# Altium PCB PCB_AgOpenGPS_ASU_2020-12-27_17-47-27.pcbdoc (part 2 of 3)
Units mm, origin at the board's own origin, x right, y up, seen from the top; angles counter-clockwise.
Board outline 200.19 x 135.91 mm, 2 copper layers (Top Layer, Bottom Layer); 260 components, 183 nets, 970 pads, 382 vias.
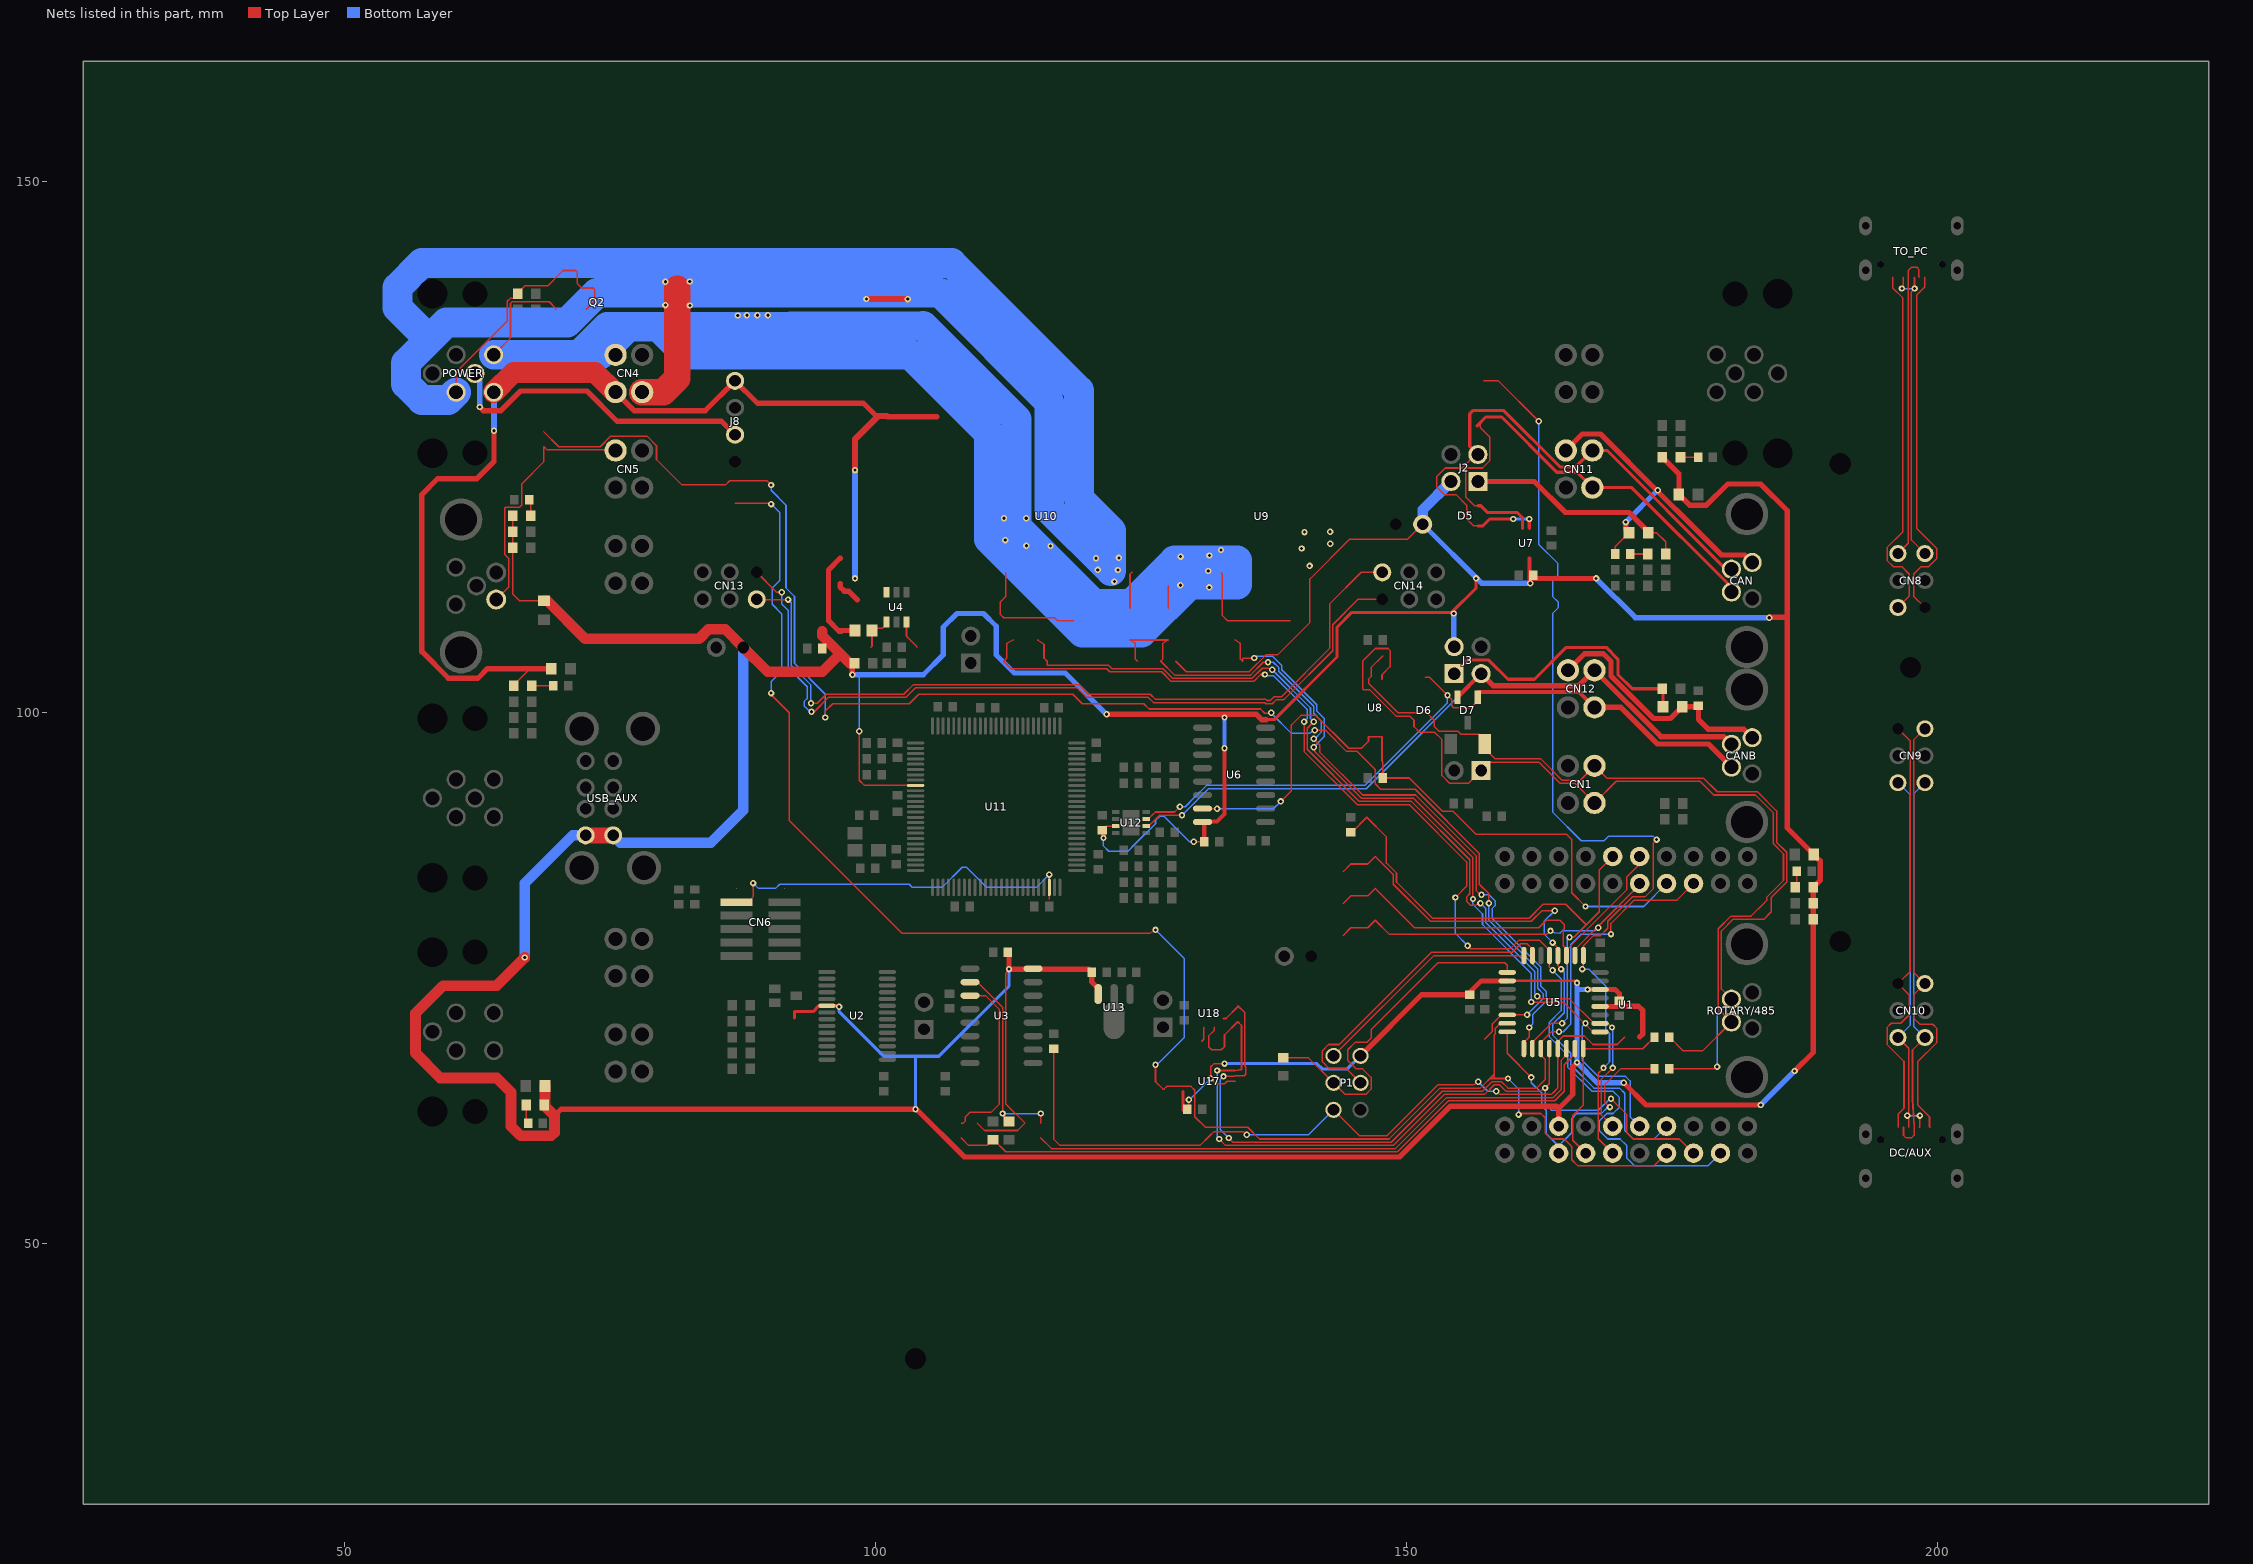
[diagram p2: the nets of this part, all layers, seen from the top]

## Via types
v1: diameter 0.6, hole 0.3, Top Layer to Bottom Layer, 381 vias
v2: diameter 0.61, hole 0.305, Top Layer to Bottom Layer, 1 vias

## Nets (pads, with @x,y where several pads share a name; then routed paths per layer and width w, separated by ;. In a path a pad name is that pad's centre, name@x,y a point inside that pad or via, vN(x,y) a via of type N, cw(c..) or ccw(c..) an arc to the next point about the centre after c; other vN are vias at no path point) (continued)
+5V: 5V.2 C2.1 C4.1 C11.1 C14.1 C22.1 C26.1 C34.1 C35.1 C40.1 C53.1 CHA.2 CHB.2 CN7.1 F1.2 F5.1 F6.1 F7.1 FGNSS.1 FROT.1 FSER.1 FWAS.1 J1.2 J2.2 J3.2 L8.2 P1.2 R6.2 R22.2 R23.2 R48.1 U1.31 U2.20 U3.16 U5.4 U5.6 U5.18 U6.16 U7.3 U11.9 U12.3 U13.3 U17.5 U17.8 USB_AUX.1 USB_AUX.5 WAS1.2 WAS2.2 | length 680.2
  Top Layer w0.145: FWAS.1@65.837,118.5 65.837,111.15 66.488,110.499 F5.1@68.786,110.499 ; FGNSS.1@68.837,63 68.887,63.05 F1.2@68.887,64.8 ; v1(98.486,98.2) 98.486,93.601 98.987,93.1 U11.9@103.787,93.1 ; R22.2@109.587,61.3 110.287,60.6 110.487,60.6 ; C40.1@121.387,88.9 121.757,89.27 U12.3@122.655,89.27 ; R48.1@128.287,104.8 129.286,103.799 135.187,103.799 136.787,105.399 137.887,105.399 140.937,108.45 140.937,112.552 144.687,116.301 150.158,116.301 J1.2@151.557,117.7 ; C14.1@129.387,62.6 129.537,62.75 v1(129.537,63.5) ; v1(129.987,87.8) C4.1@130.987,87.8 ; v1(132.887,66.9) 131.887,66.9 131.588,66.601 131.588,65.501 132.087,65 132.887,65 133.138,65.251 U17.8@133.89,65.251 ; CHB.2@188.337,80.5 188.337,83.5 188.887,84.05 188.887,86.1 F6.1@188.387,86.6
  Top Layer w0.15: 110.487,60.6 113.388,60.6 R23.2@114.087,61.3 112.286,63.1 112.287,75.4 v1(112.587,75.8) 112.632,75.845 U3.16@114.859,75.845
  Top Layer w0.25: U5.18@159.518,74.69 166.089,74.69 v1(166.087,74.5)
  Top Layer w0.3: C26.1@92.387,71.2 92.388,71.8 94.138,71.8 94.689,72.354 95.444,72.354 96.541,72.353 96.587,72.306 v1(96.587,72.25) ; U17.5@128.988,64.251 128.987,62.5 C14.1@129.387,62.6 ; 136.924,99.301 137.587,99.301 143.488,105.201 143.488,108 144.887,109.4 148.588,109.4 154.288,109.4 156.586,111.701 v1(156.587,112.6)
  Top Layer w0.35: U7.3@161.617,114.468 161.617,112.22 v1(161.687,112.15)
  Top Layer w0.4: U6.16@130.815,89.655 U6.16@130.987,89.483 ; C4.1@130.987,87.8 U6.16@130.987,89.483 ; v1@132.888,96.6 132.888,90.4 132.187,89.699 130.988,89.699 U6.16@130.988,89.483
  Top Layer w0.45: C22.1@155.987,73.4 155.987,73.601 157.077,74.69 U5.18@159.518,74.69 ; U5.4@168.255,72.283 170.087,72.283 170.087,73.5 169.688,73.88 ; U5.6@168.255,73.88 169.667,73.88
  Top Layer w0.5: 69.787,62.001 70.386,62.6 103.886,62.6 108.387,58.099 149.386,58.099 154.186,62.9 164.148,62.9 164.366,62.681 ; v1(97.837,103.526) 5V.2@97.837,104.6 ; C35.1@112.487,77.4 112.587,77.3 v1(112.587,75.8) 120.087,75.8 C53.1@120.387,75.5 ; C53.1@120.386,75.501 120.386,74.599 120.988,74 U13.3@120.987,73.45 ; C40.1@121.387,88.9 121.487,88.8 v1(121.487,88.15) ; v1(121.787,99.8) 135.887,99.8 136.387,99.3 136.837,99.3 ; P1.2@145.699,67.632 151.467,73.4 C22.1@155.987,73.4 ; C2.1@161.987,112.9 161.986,112.6 v1(167.887,112.6) ; U1.31@164.367,61 164.367,62.68 165.687,64 165.687,66.6 v1(166.087,67) ; v1(167.087,73.881) U5.6@168.256,73.881 ; C34.1@170.087,72.801 170.087,72.3 171.885,72.3 172.286,71.899 172.286,69.699 171.986,69.4 ; v1(170.487,65.1) 172.587,63 v1(183.387,63) ; FSER.1@174.137,124 175.687,122.45 F7.1@175.687,120.5 176.688,119.501 178.288,119.501 180.287,121.5 183.388,121.5 185.888,119.001 185.888,89.1 F6.1@188.387,86.6 188.987,86 188.987,84.15 188.337,83.5 188.337,67.95 ; v1(184.187,108.9) 184.23,108.943 185.888,108.943 ; v1(186.587,66.2) 188.337,67.95 ; 188.337,68.815 188.337,67.95
  Top Layer w1: v1(66.987,76.9) 64.339,74.251 59.287,74.251 56.688,71.65 56.688,67.898 59.038,65.549 64.339,65.549 65.687,64.2 65.687,61 66.587,60.101 69.487,60.101 69.787,60.4 69.787,62.001 68.888,62.9 F1.2@68.887,64.8 ; F5.1@68.786,110.499 69.086,110.499 72.688,106.9 83.386,106.9 84.288,107.799 85.858,107.799 CN7.1@87.557,106.1 89.858,103.799 94.986,103.799 96.688,105.501 ; 94.987,107.6 94.987,107.2 96.687,105.5 ; 5V.2@97.837,104.6 97.587,104.6 96.687,105.5
  Top Layer w1.5: USB_AUX.1@72.712,88.4 USB_AUX.5@75.313,88.4
  Bottom Layer w0.145: v1(98.486,98.2) 98.486,103.526 ; v1(121.487,88.15) 121.487,87.4 121.987,86.9 123.787,86.9 124.487,87.6 126.387,89.5 126.387,89.8 126.787,90.2 127.187,90.2 127.587,89.8 129.587,87.8 v1(129.987,87.8) ; v1(129.537,63.5) 129.587,63.5 v1(131.587,65.5)
  Bottom Layer w0.3: v1(96.587,72.25) 96.587,71.8 100.787,67.6 105.987,67.6 112.587,74.2 v1(112.587,75.8) ; v1(103.787,62.6) 103.787,67.6 ; v1(132.887,66.9) 141.587,66.9 142.087,66.4 144.467,66.4 P1.2@145.699,67.632
  Bottom Layer w0.4: v1@132.887,96.6 v1(132.887,99.5)
  Bottom Layer w0.5: v1@97.836,103.525 104.514,103.525 106.388,105.399 106.388,108 107.686,109.3 110.188,109.3 111.387,108.099 111.387,105.399 113.086,103.7 117.887,103.7 v1@121.788,99.801 ; J1.2@151.557,117.7 157.107,112.15 v1(161.687,112.15) ; v1@154.487,109.3 154.487,106.2 J3.2@154.517,106.17 ; v1@166.086,66.999 166.086,74 166.205,73.88 v1(167.087,73.881) ; v1(166.087,67) 167.987,65.1 v1(170.487,65.1) ; 166.087,73.9 v1(166.087,74.5) ; v1(167.887,112.6) 171.587,108.9 v1(184.187,108.9) ; v1(183.387,63) v1@186.587,66.2
  Bottom Layer w1: v1(66.987,76.9) 66.988,83.9 71.486,88.399 USB_AUX.1@72.712,88.4 ; USB_AUX.5@75.311,88.399 75.987,87.7 84.486,87.7 87.557,90.771 CN7.1@87.557,106.1 ; J1.2@151.557,117.7 151.557,119.07 J2.2@154.217,121.73
  other v1: 132.887,96.6 154.487,109.3
+BATT: C17.2 C18.2 C19.2 C32.1 CN4.2 D2.1 F4.1 FINP.1 J8.4 POWER.1 U4.3 | length 113.2
  Top Layer w0.145: FINP.1@65.937,102.5 65.937,102.55 67.487,104.1 F4.1@69.487,104.1
  Top Layer w0.5: v1@64.087,126.501 64.087,123.601 62.487,122 58.786,122 57.288,120.499 57.288,105.701 59.787,103.199 62.586,103.199 63.488,104.101 F4.1@69.487,104.101 ; CN4.2@75.537,130.15 77.287,128.4 83.977,128.4 J8.4@86.787,131.21 88.897,129.1 98.887,129.1 100.087,127.9 C32.1@101.087,127.9 101.152,127.835 D2.1@105.787,127.835 ; C17.2@96.687,112.1 96.688,111.8 97.087,111.401 97.488,111.401 98.288,110.601
  Top Layer w0.6: v1@98.088,122.801 98.088,125.701 100.287,127.901 101.087,127.901
  Top Layer w2: POWER.1@64.054,130.131 65.924,132 73.588,131.994 CN4.2@75.487,130.151
  Bottom Layer w0.6: POWER.1@64.055,130.132 64.087,130.1 v1(64.087,126.5) ; v1(98.087,112.6) v1(98.087,122.8)
+MOTOR: C30.2 C31.1 CN4.1 D1.1 MOT.2 POWER.4 Q2.2 R51.2 R53.2 U9.7 U10.7 | length 231.6
  Top Layer w0.145: POWER.4@60.519,130.132 60.519,132.031 65.337,136.849 65.337,138.701 65.639,139.001 66.338,139.001 MOT.2@66.337,139.4 ; MOT.2@66.338,139.407 66.338,139.501 66.988,140.149 69.137,140.149 70.437,141.449 70.587,141.6 ; 123.988,109.801 123.988,113.001 C30.2@124.187,113.2
  Top Layer w0.15: 70.587,141.599 71.789,141.599 71.938,141.449 71.938,140.349 72.337,139.951 73.437,139.951 73.587,139.801 73.587,138.757 Q2.2@72.771,137.94
  Top Layer w0.6: v1(99.155,138.912) v1(103.053,138.907)
  Top Layer w2.5: CN4.1@78.037,130.151 80.038,130.151 81.352,131.465 D1.1@81.352,139.9
  Bottom Layer w2.8: 57.986,135.089 54.986,138.089 54.986,140.001 57.285,142.3 107.186,142.3 119.187,130.299 119.187,120.101 122.187,117.101 122.187,113.301 116.388,119.1 116.388,129.239 106.124,139.501 ; POWER.4@60.519,130.132 59.787,129.4 57.288,129.4 55.787,130.901 55.787,132.9 59.586,136.699 70.986,136.699 73.787,139.501 106.086,139.501
  other v1: 122.517,112.301 122.842,113.396 120.947,113.406 140.904,113.779 120.779,114.495 122.939,114.532 140.152,115.416 142.842,115.858 140.425,116.958 142.833,116.996 82.535,138.3 80.224,138.338 80.224,140.548 82.522,140.561
+SMPS: C20.2 C21.2 L7.2 L8.1 R17.2 | length 9.5
  Top Layer w0.5: C21.2@96.687,114.5 95.588,113.4 95.588,108.617 96.604,107.601 ; 96.787,107.601 96.604,107.601 ; R17.2@98.087,107.7 96.703,107.7 96.604,107.601
-MOTOR: C30.1 C31.2 CN4.4 D1.2 POWER.2 R11.1 R12.1 R20.2 R21.2 R49.1 R54.2 U9.1 U10.1 | length 206.3
  Top Layer w0.145: POWER.2@64.054,133.669 65.639,135.252 65.639,138.498 65.792,138.65 ; U10.1@112.277,113.116 112.277,110.89 111.787,110.4 111.787,109.2 112.087,108.9 116.888,108.9 R21.2@117.187,108.6 R20.2@118.687,108.6 ; R54.2@127.587,109.8 127.587,111.9 ; U9.1@132.577,113.116 132.687,113.006 132.687,109.1 133.187,108.6 R11.1@137.587,108.6 R12.1@139.087,108.6
  Top Layer w0.15: 65.787,138.65 69.287,138.65 69.887,138.05 R49.1@69.887,137.9
  Bottom Layer w2.8: POWER.2@64.054,133.669 74.067,133.669 76.698,136.301 ; 72.162,133.682 74.793,136.313 ; 74.76,136.301 76.698,136.301 ; 79.185,136.301 104.487,136.4 113.287,127.601 113.287,117.5 120.587,110.2 124.087,110.2 128.187,114.299 134.087,114.299 134.087,112.001 129.586,112.001 125.085,107.5 119.487,107.5 110.686,116.301 110.686,126.301 103.287,133.7 82.187,133.7 79.586,136.301 76.698,136.301
  other v1: 131.452,111.759 128.734,111.953 131.349,113.294 128.756,114.65 131.461,114.752 132.555,115.282 116.504,115.651 114.229,115.668 112.229,116.206 112.115,118.266 114.215,118.263 87.04,137.366 87.904,137.379 88.894,137.379 89.885,137.379
.8V: R17.1 R18.2 U4.4 | length 3.5
  Top Layer w0.145: R18.2@99.587,106.1 99.687,106.2 R17.1@99.687,107.7 99.887,107.9 100.687,107.9 101.037,108.25 U4.4@101.037,108.5
_RESET: C7.1 P1.5 R6.1 U5.29 | length 73.3
  Top Layer w0.145: C7.1@116.787,68.3 116.787,59.8 117.387,59.2 130.587,59.2 131.487,60.1 131.887,60.5 133.287,60.5 134.687,60.5 v1(134.987,60.2) ; P1.5@143.159,62.552 145.611,60.101 148.187,60.101 152.987,64.901 156.387,64.9 v1@156.787,65.201 ; v1(158.487,64.3) 158.787,64 160.387,64 163.687,64 163.887,64.2 164.281,64.594 U5.29@164.281,68.319 164.281,68.994 164.787,69.5 166.787,69.5 167.587,68.7 169.887,68.7 R6.1@170.587,69.4
  Bottom Layer w0.145: v1(134.987,60.2) 140.807,60.2 P1.5@143.159,62.552 ; v1(156.787,65.2) 157.687,64.3 v1(158.487,64.3)
_RESETNXP: CN6.10 U11.48 | length 35.8
  Top Layer w0.145: CN6.10@86.937,82.105 87.992,82.105 88.487,82.6 v1@88.487,83.9 ; 116.387,82.4 U11.48@116.387,83.5 v1(116.387,84.7)
  Bottom Layer w0.145: v1@88.486,83.9 88.987,83.4 90.587,83.4 90.988,83.799 103.188,83.799 103.488,83.499 106.287,83.499 108.187,85.399 108.588,85.399 110.488,83.499 115.187,83.499 v1@116.388,84.701
  other v1: 88.487,83.9
_RXD: R9.2 RXD.1 U3.2 | length 19.6
  Top Layer w0.145: U3.2@108.915,74.575 109.613,74.575 111.987,72.201 111.987,62.049 RXD.1@112.586,61.449 ; R9.2@115.587,61.3 v1(115.587,62.2)
  Bottom Layer w0.145: v1(111.987,62.2) v1(115.587,62.2)
_TXD: R7.1 U3.3 | length 16.8
  Top Layer w0.145: R7.1@108.087,61.3 108.288,61.3 108.486,61.5 108.486,61.899 108.888,62.3 110.887,62.3 111.687,63.101 111.687,72 110.382,73.305 U3.3@108.915,73.305
A: CN1.4 D6.1 J4.1 R32.1 R37.1 R90.1 ROTARY/485.4 U8.6 | length 90
  Top Layer w0.145: R37.1@146.387,105.3 147.087,106 148.287,106 148.487,105.8 148.487,104.3 147.722,103.535 U8.6@147.722,103.12 ; R37.1@146.387,105.3 145.888,104.8 145.888,102.201 145.987,102.1 146.586,102.1 149.088,99.6 150.386,99.6 150.737,99.25 150.737,99.001 150.737,98.65 151.288,98.099 152.688,98.099 153.363,97.423 153.363,94.025 154.087,93.301 155.857,93.301 157.056,94.5 157.056,95.3 162.487,95.3 164.488,93.301 165.888,93.301 CN1.4@167.737,91.45 169.787,93.499 177.663,93.499 178.961,92.201 182.888,92.201 184.587,90.499 184.587,87.599 185.537,86.651 185.537,84.15 183.945,82.557 183.945,82.258 R32.1@183.687,82 182.487,80.799 180.587,80.799 179.388,79.6 179.388,72.074 ROTARY/485.4@180.637,70.825 ; R90.1@174.787,69.4 176.089,68.099 177.915,68.099 ROTARY/485.4@180.427,70.614
A0/WAS: C9.2 R28.2 U1.16 U5.23 U17.4 | length 159.5
  Top Layer w0.145: R28.2@86.787,119.7 90.087,119.7 v1(90.187,119.6) ; v1(90.187,101.8) 90.188,101.65 91.888,99.951 91.888,89.798 102.487,79.199 125.888,79.199 v1@126.388,79.501 ; v1(126.387,66.8) 126.387,65.2 127.087,64.5 C9.2@127.187,64.5 127.438,64.751 U17.4@128.988,64.751 ; U17.4@128.988,64.751 129.736,64.749 130.087,64.398 130.087,61.899 131.087,60.898 135.088,60.898 136.188,59.801 137.287,59.801 148.387,59.801 153.188,64.599 156.988,64.599 158.288,65.902 158.288,69.6 158.387,69.699 158.387,70.2 158.88,70.692 U5.23@159.518,70.692 ; 157.821,65.433 157.888,65.501 158.288,65.501 ; 158.288,66.339 158.288,65.501 ; v1@159.586,65.501 158.288,65.501 ; v1(160.587,62.1) 160.686,62.201 162.687,62.201 163.086,61.8 163.086,60.4 163.688,59.801 164.887,59.801 165.588,59.1 165.588,57.853 166.139,57.299 173.368,57.299 U1.16@174.526,58.46
  Bottom Layer w0.145: v1(90.187,101.8) 90.188,102.9 91.186,103.9 91.186,109.257 90.287,110.156 90.287,111.701 90.988,112.402 90.988,118.8 v1(90.187,119.6) ; v1@126.388,66.801 126.538,66.801 129.088,69.349 129.088,76.801 v1@126.388,79.501 ; v1(159.587,65.5) 160.587,64.5 v1(160.587,62.1)
  other v1: 126.387,79.5
A1/CH_B: R91.2 U1.32 U5.24 | length 28.9
  Top Layer w0.145: U5.24@159.518,69.893 159.518,67.869 v1(161.787,65.6) ; v1@169.187,62.801 168.687,63.301 168.687,64.899 170.188,66.4 R91.2@173.386,66.4
  Bottom Layer w0.145: v1(161.787,65.6) 161.787,65.1 162.787,64.1 162.787,62.936 163.187,62.5 163.187,60.3 164.366,59.121 164.366,58.46 164.366,59.179 165.588,60.4 165.588,61.701 166.089,62.201 168.387,62.201 168.987,62.801 v1@169.187,62.801
  other v1: 169.187,62.8
A2/SAFESENSE: R25.1 R48.2 R53.1 R54.1 U5.25 | length 72.2
  Top Layer w0.145: R25.1@124.687,104.8 124.486,105 124.486,106.499 R53.1@123.987,106.8 R54.1@127.587,106.8 127.087,106.499 127.087,105 126.886,104.8 128.187,103.499 135.337,103.499 136.538,104.701 v1@136.988,104.701 ; v1(141.287,97.5) 141.847,96.941 141.847,96.263 145.911,92.201 150.887,92.201 156.586,86.499 156.586,83.199 156.986,82.8 v1(157.087,82.8) ; U5.25@161.082,68.318 161.082,68.897 161.588,69.4 v1@161.588,70.301
  Bottom Layer w0.145: v1@136.988,104.701 137.488,104.701 137.986,104.2 137.986,103.85 141.288,100.55 141.288,99.9 141.986,99.199 141.986,98.099 141.387,97.5 v1(141.287,97.5) ; v1@157.087,82.801 157.808,82.801 158.387,82.222 158.387,81.8 158.088,81.5 158.088,80.601 162.682,76.006 162.682,74.205 163.188,73.699 163.188,72.801 161.937,71.55 161.937,70.65 v1(161.587,70.3)
  other v1: 136.987,104.7
A3/OUT: R33.2 R77.1 U1.21 U5.26 | length 52.1
  Top Layer w0.145: R77.1@144.787,88.7 144.887,88.7 R33.2@146.287,90.1 148.137,88.25 148.137,85.796 149.088,84.845 149.087,84 152.487,80.6 161.587,80.6 162.887,81.9 165.036,81.9 166.961,79.974 ; U5.26@161.883,68.319 161.883,68.896 163.687,70.7 v1(164.687,70.7) ; v1(165.387,78.8) 165.787,78.8 167.287,80.3 168.187,81.2 168.187,83 168.187,85.14 U1.21@169.447,86.4
  Bottom Layer w0.145: v1(164.687,70.7) 165.187,71.2 165.187,78.8 v1(165.387,78.8)
A4/SDA: R30.1 U1.10 U5.27 U17.9 U18.6 | length 79.2
  Top Layer w0.145: v1(132.787,65.7) 133.84,65.7 U17.9@133.89,65.751 134.738,65.751 134.887,65.9 134.887,66.6 134.787,66.7 134.787,71.703 134.139,72.351 134.139,72.252 133.038,71.151 U18.6@132.789,71.151 ; v1(133.287,59.9) 133.688,59.501 148.588,59.501 153.386,64.299 157.188,64.299 158.09,65.201 158.987,65.201 159.589,64.599 162.286,64.599 163.086,65.399 163.086,67.299 162.682,67.703 U5.27@162.682,68.318 ; U5.27@162.683,68.319 162.683,68.896 163.687,69.9 v1(164.387,69.9) ; v1(169.287,79.1) 169.287,80.1 171.487,82.3 175.507,82.3 U1.10@177.067,83.86
  Bottom Layer w0.145: v1(132.787,65.7) 132.487,65.399 132.487,60.7 v1(133.287,59.9) ; v1(164.387,69.9) 164.788,69.9 165.487,70.601 165.487,78.099 166.487,79.1 v1(169.287,79.1)
A5/SCL: R29.1 U1.12 U5.28 U17.10 U18.4 | length 77
  Top Layer w0.145: U18.4@131.939,70.301 131.939,70.052 131.387,69.5 131.387,68.5 131.687,68.2 132.587,68.2 132.887,68.5 132.887,69.599 R29.1@134.139,70.851 134.488,70.503 134.488,66.348 U17.10@133.89,66.251 v1(132.187,66.25) ; v1@132.388,59.801 132.987,59.199 148.786,59.199 153.587,64 157.387,64 158.288,64.901 158.786,64.901 159.388,64.299 162.587,64.3 v1@163.086,64.599 ; v1(163.087,64.6) 163.483,64.996 U5.28@163.483,68.319 ; v1@169.286,63.601 170.788,62.1 170.788,60.4 171.387,59.801 175.728,59.801 U1.12@177.066,58.46
  Bottom Layer w0.145: v1(132.187,66.25) 132.187,60 v1(132.387,59.8) ; v1@163.086,64.599 163.086,63.1 163.688,62.501 168.088,62.501 169.187,63.601 v1@169.286,63.601
  other v1: 169.287,63.6
A7: C33.2 R5.2 R56.2 U5.22 | length 143.1
  Top Layer w0.145: 68.786,126.4 70.186,125 74.087,125 75.088,126.001 78.486,126.001 79.388,125.099 79.388,123.801 81.794,121.401 85.888,121.401 86.287,121.8 87.288,121.8 89.787,121.8 v1(90.187,121.4) ; v1@95.286,99.501 95.286,100.101 95.987,100.799 103.185,100.799 104.087,101.701 118.588,101.701 119.487,100.799 125.286,100.799 125.786,100.301 136.287,100.301 136.688,99.9 v1@137.287,99.9 ; v1(141.387,98.3) 142.388,98.3 144.387,96.301 145.388,96.301 R5.2@146.387,95.3 147.087,94.599 147.087,93.25 147.587,92.75 150.846,92.75 156.886,86.7 156.886,83.799 157.788,82.9 v1@157.788,82.001 ; C33.2@157.387,69.2 158.088,69.9 158.088,70.601 158.982,71.493 U5.22@159.518,71.493 ; U5.22@159.518,71.494 161.381,71.493 v1(161.387,71.5)
  Bottom Layer w0.145: v1@90.188,121.401 90.188,120.901 91.588,119.501 91.588,111.701 92.388,110.901 92.388,104.599 95.286,101.701 v1@95.286,99.501 ; v1@137.287,99.9 139.187,98 140.887,98 v1(141.387,98.3) ; v1@157.788,82.001 157.788,80.4 162.385,75.803 162.385,74.002 162.888,73.499 162.888,73.001 v1(161.387,71.5)
  other v1: 157.787,82 95.287,99.5 137.287,99.95
AUX: J8.2 POWER.5 | length 30
  Top Layer w0.5: v1(62.737,128.75) 63.086,128.399 64.737,128.399 66.587,130.25 72.838,130.25 75.687,127.401 85.517,127.401 J8.2@86.787,126.13
  Bottom Layer w0.5: POWER.5@62.287,131.9 62.737,131.45 v1(62.737,128.75)
B: CN1.2 D6.2 R31.1 R38.1 R91.1 R92.2 ROTARY/485.2 U8.7 | length 82.9
  Top Layer w0.145: 146.452,103.121 146.688,103.354 146.688,104.2 R38.1@147.787,105.3 ; U8.7@146.452,103.12 146.452,102.735 149.259,99.929 151.958,99.929 152.637,99.25 D6.2@152.637,99 ; 152.637,99.001 152.637,98.65 153.086,98.201 154.887,98.201 155.187,97.901 156.886,97.901 157.387,97.401 R92.2@157.387,97 ; R92.2@157.087,96.199 157.785,96.199 158.387,95.6 162.687,95.6 164.686,93.601 166.386,93.601 CN1.2@167.737,94.95 ; CN1.2@167.737,94.95 168.888,93.799 173.555,93.799 ; 173.188,93.799 177.988,93.799 179.286,92.501 183.086,92.501 184.887,90.7 184.887,87.751 185.837,86.801 185.837,84 184.387,82.549 184.387,81.2 R31.1@183.687,80.5 ; R91.1@174.787,66.4 179.087,66.4 v1@179.287,66.6 ; ROTARY/485.2@180.637,72.975 179.687,73.925 179.687,79.4 180.787,80.5 R31.1@183.687,80.5
  Bottom Layer w0.145: v1(179.287,66.6) 179.287,71.623 ROTARY/485.2@180.637,72.975
C8_2: C8.2 U18.2 | length 1.4
  Top Layer w0.145: C8.2@130.737,69 130.939,69.202 U18.2@130.939,70.301
C16_1: C16.1 U4.6 | length 2.8
  Top Layer w0.145: U4.6@102.937,108.5 102.937,107.151 103.887,106.2 C16.1@103.887,106.1
CAN+: CAN.1 CN11.1 F2.2 R71.2 | length 31.2
  Top Layer w0.145: R71.2@169.687,114.9 169.687,115.6 F2.2@170.987,116.9
  Top Layer w0.5: CN11.1@165.037,124.65 166.586,126.199 168.288,126.199 170.988,123.499 ; v1(170.687,117.9) 170.687,117.2 F2.2@170.987,116.9 ; CAN.1@182.588,114.101 181.887,114.8 179.683,114.8 171.036,123.446 ; 170.988,123.499 171.036,123.446 ; 170.988,123.499 171.036,123.446
  Bottom Layer w0.5: v1(170.687,117.9) v1(173.687,120.9)
CANB+: CANB.1 CN12.1 F3.2 R72.2 | length 23.7
  Top Layer w0.5: CN12.1@165.237,103.95 166.787,105.5 168.587,105.5 169.287,104.8 169.287,103.4 173.287,99.4 174.887,99.4 F3.2@175.987,100.5 177.533,100.5 177.533,99.304 178.437,98.4 181.788,98.4 CANB.1@182.587,97.6
CANH: CAN.4 CN11.4 D5.2 R60.1 U7.7 | length 47.5
  Top Layer w0.145: D5.2@156.787,119.45 156.437,119.45 155.588,120.301 155.588,122.806 155.784,123.001 157.188,123.001 157.887,123.7 157.887,125.899 156.988,126.801 156.988,127.101
  Top Layer w0.3: 156.698,126.987 157.511,127.799 158.987,127.799 164.186,122.6 166.089,122.6 CN11.4@167.537,121.15 171.237,121.15 180.638,111.749 CAN.4@180.637,111.325 ; D5.2@156.787,119.45 157.036,119.45 157.686,118.8 160.488,118.8 160.958,118.33 U7.7@160.957,117.333
CANH1: CANB.4 CN12.4 D7.1 R65.1 U12.7 | length 68
  Top Layer w0.145: U12.7@125.52,89.93 125.717,89.93 126.187,90.4 126.387,90.6 127.187,90.6 128.187,90.6 v1(128.687,91.1) ; R65.1@151.787,103.3 152.187,103.3 154.287,101.2 154.287,100.6 154.487,100.4 156.087,100.4 156.737,101.05 D7.1@156.737,101.4
  Top Layer w0.4: D7.1@156.737,101.4 156.79,101.899 166.289,101.899 CN12.4@167.737,100.451
  Top Layer w0.5: CN12.4@167.737,100.451 170.236,100.451 173.688,96.999 178.463,96.999 CANB.4@180.637,94.825
  Bottom Layer w0.145: v1(128.687,91.1) 129.187,91.1 130.087,92 131.187,93.1 131.787,93.1 146.087,93.1 153.887,100.9 v1@153.887,101.6
  other v1: 153.887,101.6
CANL: CAN.2 CN11.2 D5.1 J2.3 U7.6 | length 54.2
  Top Layer w0.145: J2.3@156.757,124.271 156.558,124.271 155.288,123.001 153.688,123.001 152.888,122.201 152.888,121.2 153.587,120.499 154.686,120.499 155.687,119.501 155.687,118.201 156.337,117.55 D5.1@156.787,117.55
  Top Layer w0.3: J2.3@156.757,124.27 155.987,125.041 155.987,128.099 156.287,128.401 159.187,128.401 164.488,123.1 165.987,123.1 167.536,124.65 168.936,124.65 180.112,113.476 CAN.2@180.638,113.476 ; D5.1@156.787,117.55 157.237,117.55 157.887,118.201 v1@160.087,118.201 ; v1(161.587,118.2) 161.587,117.363 U7.6@161.617,117.333
  Bottom Layer w0.3: v1(160.087,118.2) v1(161.587,118.2)
CANL1: CANB.2 CN12.2 D7.2 J3.3 U12.6 | length 68.7
  Top Layer w0.145: U12.6@125.52,89.27 125.757,89.27 126.087,89.6 126.787,90.3 v1(128.887,90.3)
  Top Layer w0.4: D7.2@154.836,101.401 J3.3@157.056,103.631 ; D7.2@154.837,101.4 155.241,101.807
  Top Layer w0.5: J3.3@157.057,103.63 158.187,102.5 166.286,102.5 167.737,103.951 173.988,97.7 179.911,97.7 CANB.2@180.637,96.975
  Bottom Layer w0.145: v1(128.887,90.3) 131.387,92.8 146.227,92.8 J3.3@157.057,103.63
CC11: CN8.1 TO_PC.A5 | length 34
  Top Layer w0.145: TO_PC.A5@198.837,140.985 198.837,140.05 198.087,139.3 198.087,117.3 199.987,115.4 199.987,114.5 199.187,113.7 198.487,113.7 197.787,113 197.787,110.93 CN8.1@198.857,109.86
CC12: CN9.1 CN10.1 DC/AUX.A5 | length 41.2
  Top Layer w0.145: CN10.1@196.317,74.44 197.386,73.37 197.386,71.5 196.586,70.7 195.687,70.7 195.288,70.301 195.288,68.701 196.886,67.101 196.887,62.7 196.337,62.15 DC/AUX.A5@196.337,60.915 ; CN9.1@196.317,98.44 197.487,97.27 197.487,75.61 CN10.1@196.317,74.44
CC21: CN8.2 TO_PC.B5 | length 33.9
  Top Layer w0.145: TO_PC.B5@195.837,140.985 195.837,139.951 196.787,139.001 196.787,116.999 195.288,115.501 195.288,114.299 195.888,113.7 196.688,113.7 197.386,113.001 197.386,110.931 CN8.2@196.317,109.86
CC22: CN9.2 CN10.2 DC/AUX.B5 | length 41.7
  Top Layer w0.145: CN10.2@198.857,74.44 197.788,73.37 197.788,71.2 198.387,70.601 199.586,70.601 199.987,70.2 199.987,68.899 198.187,67.098 198.187,63.001 199.286,61.899 199.286,60.964 199.337,60.916 ; CN9.2@198.857,98.44 197.787,97.37 197.787,75.51 CN10.2@198.857,74.44
CN5_4: CN5.4 OP1.2 R56.1 R57.1 | length 24.2
  Top Layer w0.145: OP1.2@64.288,110.611 65.487,111.81 65.487,114.449 65.088,114.85 65.088,116.28 65.088,116.4 65.088,119.199 65.187,119.3 66.488,119.3 66.687,119.5 66.688,119.651 66.688,121.5 68.786,123.601 ; R57.1@68.787,123.6 R56.1@68.787,125 69.087,124.7 75.487,124.7 CN5.4@75.537,124.65
CN13_1: CN13.1 CN14.1 | length 76.7
  Top Layer w0.145: CN13.1@88.827,113.17 90.697,111.3 v1(91.187,111.3) ; v1(93.987,100.05) 94.237,100.05 95.588,101.401 102.888,101.401 103.787,102.3 118.984,102.3 119.883,101.401 125.687,101.401 126.188,100.901 135.388,100.901 136.668,100.901 136.767,100.799 137.387,100.799 137.747,101.16 138.448,101.16 138.512,101.223 ; 138.486,101.2 143.084,105.798 143.084,108.246 145.469,110.631 147.747,110.631
  Bottom Layer w0.145: v1(91.187,111.3) 91.186,110.2 91.786,109.6 91.786,104.2 93.589,102.397 93.589,101.302 93.287,101 93.287,100.601 93.838,100.05 v1(93.987,100.05)
CN13_2: CN13.2 CN14.2 | length 76.2
  Top Layer w0.145: CN13.2@88.827,110.63 88.857,110.6 v1(91.787,110.6) ; v1(93.937,100.85) 94.537,100.85 95.388,101.701 102.688,101.701 103.587,102.6 119.149,102.6 120.048,101.701 125.888,101.701 126.388,101.2 136.787,101.2 136.886,101.101 137.188,101.101 137.544,101.457 138.245,101.457 142.787,106.001 142.787,110.2 145.758,113.171 CN14.2@147.747,113.171
  Bottom Layer w0.145: v1@91.786,110.601 92.087,110.3 92.087,104.401 93.937,102.551 v1(93.937,100.85)
D0/RX: R9.1 U5.30 | length 55.8
  Top Layer w0.145: R9.1@115.587,59.9 116.587,58.9 148.987,58.9 153.787,63.7 163.844,63.7 164.587,64.443 164.587,67.2 165.081,67.694 U5.30@165.081,68.319
D1/TX: R7.2 TXD.1 U5.31 | length 64.6
  Top Layer w0.145: R7.2@108.087,59.9 108.787,59.2 110.537,59.2 TXD.1@111.087,59.75 111.138,59.75 112.286,58.6 149.187,58.6 153.988,63.4 163.988,63.4 164.887,64.299 164.887,66.801 165.88,67.794 U5.31@165.88,68.318
D2/CH_A: R90.2 U1.28 U5.32 | length 17.9
  Top Layer w0.145: U5.32@166.68,68.3 172.286,68.3 R90.2@173.386,69.4 ; U5.32@166.681,68.319 166.681,62.994 165.687,62 165.687,59.68 U1.28@166.907,58.46
D3/PWM0: R27.1 R55.1 U1.19 U5.1 | length 73.3
  Top Layer w0.145: R55.1@133.887,106.8 134.387,106.499 134.387,105 R27.1@134.587,104.8 134.587,105.099 v1(135.687,105.1) ; v1(141.287,96.7) 141.387,96.7 141.387,96.301 145.786,91.899 150.686,91.899 156.287,86.301 v1(156.287,82.4) ; v1(161.787,72.7) 164.788,72.699 167.605,69.882 U5.1@168.255,69.882
  Bottom Layer w0.145: v1(135.687,105.1) 135.687,105.249 137.437,105.249 138.283,104.403 138.283,104.005 141.585,100.703 141.585,100.103 142.286,99.4 142.286,97.7 v1(141.287,96.7) ; v1(156.287,82.4) 156.287,81.899 157.188,81 157.188,79.999 161.788,75.399 v1(161.787,72.7) ; v1@166.886,70.7 166.586,70.4 166.586,67.2 168.088,65.699 170.663,65.699 171.087,65.275 171.087,61.899 U1.19@171.986,61
  other v1: 166.887,70.7
D4/INH: R42.1 R61.1 U1.23 U5.2 | length 88.9
  Top Layer w0.145: R61.1@115.287,106.8 115.887,106.4 115.887,105.1 R42.1@116.187,104.8 ; R42.1@116.187,104.8 116.188,104.401 121.987,104.401 122.286,104.101 127.087,104.101 127.986,103.199 135.487,103.199 136.437,104.149 136.987,104.15 v1(137.387,104) ; v1(141.287,99.1) 140.683,98.495 140.683,96.504 145.588,91.599 150.488,91.599 155.987,86.1 155.987,82.9 155.687,82.6 155.687,82.201 156.086,81.8 156.487,81.8 v1@156.988,82.001 ; v1(162.337,73.25) 162.588,72.999 165.387,72.999 167.704,70.682 U5.2@168.255,70.682 ; U5.2@168.256,70.683 169.004,70.683 v1(169.387,70.3) ; U1.23@169.446,61 168.387,62.059 168.387,65.44 v1(169.447,66.5)
  Bottom Layer w0.145: v1(137.387,104) 140.988,100.398 140.988,99.397 v1@141.288,99.097 ; v1@156.988,82.001 157.488,81.5 157.488,80.2 162.088,75.597 162.088,73.499 v1(162.337,73.25) ; v1(169.387,70.3) 169.447,70.24 v1@169.447,66.5
  other v1: 156.987,82
D5/SERVO: R59.1 U1.24 U5.9 | length 92.1
  Top Layer w0.145: R59.1@157.287,131.2 158.687,131.2 v1@162.487,127.4 ; v1(166.587,75.8) 166.691,75.904 U5.9@166.691,77.082 ; U5.9@166.691,77.081 166.691,78.005 167.653,78.968 168.303,78.968 168.987,79.651 168.987,80.299 171.288,82.6 172.487,82.6 173.287,83.4 173.287,87.7 v1(173.587,88) ; v1(168.587,66.5) 168.088,66.001 168.088,59.821 U1.24@169.446,58.46
  Bottom Layer w0.145: v1@162.487,127.401 162.487,115.8 164.288,113.999 164.288,112.9 163.787,112.399 163.787,110.901 164.336,110.352 164.336,109.849 163.787,109.3 163.787,90.601 166.487,87.901 168.634,87.901 169.035,88.302 173.284,88.302 v1(173.587,88) ; v1(166.587,75.8) 167.187,75.8 168.787,74.2 168.786,70.119 169.15,69.755 169.15,67.063 v1(168.587,66.5)
  other v1: 162.487,127.4
D6/STSW: C28.2 R43.1 U1.18 U5.10 | length 34.9
  Top Layer w0.145: R43.1@144.087,79 144.787,79.7 146.387,79.7 C28.2@147.087,80.4 ; C28.2@147.087,80.4 148.387,79.1 163.287,79.1 v1(163.587,79.4) ; U5.10@165.89,77.081 165.89,77.655 167.836,79.6 167.988,79.6 v1(168.087,79.7) ; v1(168.087,79.7) 168.037,79.75 168.037,79.801 171.986,83.751 U1.18@171.986,83.86
  Bottom Layer w0.145: v1(163.587,79.4) 163.987,79.209 164.486,79.199 164.687,79.4 167.787,79.4 v1(168.087,79.7)
D7/WKSW: C29.2 R46.1 U1.17 U5.11 | length 38.6
  Top Layer w0.145: 144.087,82 144.787,82.7 146.387,82.7 C29.2@147.087,83.4 ; C29.2@147.087,83.4 150.788,79.699 162.487,79.699 163.188,80.4 164.486,80.4 164.887,79.999 164.887,79.6 164.788,79.501 164.788,77.998 165.09,77.695 U5.11@165.09,77.081 ; U5.11@165.091,77.082 165.091,77.604 170.787,83.3 170.787,84.5 171.987,85.7 U1.17@171.987,86.4
D8/RTSW: C27.2 R39.1 U1.15 U5.12 | length 55.3
  Top Layer w0.145: R39.1@144.087,85 144.787,85.7 146.387,85.7 C27.2@147.087,86.4 ; C27.2@147.087,86.4 148.786,84.701 148.786,83.799 152.286,80.301 161.788,80.301 162.787,81.3 v1(163.987,81.3) ; v1(163.787,78.3) 164.291,77.796 U5.12@164.291,77.082 ; U5.12@164.29,77.081 164.29,76.097 v1(164.587,75.8)
  Bottom Layer w0.145: v1(163.787,78.3) 162.987,79.1 162.987,80.299 v1(163.987,81.3) ; v1(164.587,75.8) 164.887,75.5 164.887,71.701 163.787,70.601 163.787,69.603 165.504,67.886 165.504,66.783 167.689,64.599 170.089,64.599 170.587,64.101 170.587,60.601 171.387,59.801 173.328,59.801 U1.15@174.526,61
D9/PWM1: R26.1 R62.2 U1.8 U5.13 | length 111.6
  Top Layer w0.145: R62.2@112.987,106.8 112.388,106.499 112.388,105.099 R26.1@112.087,104.8 112.787,104.101 121.788,104.101 122.088,103.799 126.968,103.799 127.867,102.9 135.637,102.9 136.287,103.55 v1(136.687,103.55) ; v1@140.386,99.1 140.386,96.301 145.388,91.3 150.287,91.3 155.687,85.899 155.687,83.6 v1(154.637,82.55) ; v1(155.787,78) 156.089,77.698 159.787,77.7 160.587,78.5 162.588,78.5 163.493,77.584 U5.13@163.493,77.081 ; U5.13@163.494,77.082 163.494,75.994 v1(163.787,75.7)
  Bottom Layer w0.145: v1@136.787,103.4 136.687,103.5 v1(136.687,103.55) 136.688,103.451 137.488,103.451 140.686,100.25 140.686,99.4 v1@140.46,99.174 ; v1(154.637,82.55) 154.637,79.15 v1(155.787,78) ; v1(163.787,75.7) 164.587,74.899 164.587,71.899 163.488,70.799 163.488,69.415 165.202,67.7 165.202,66.585 167.488,64.299 169.487,64.299 170.087,63.7 170.087,62.801 169.487,62.201 168.888,62.201 168.187,61.5 168.187,60.601 168.987,59.801 170.142,59.801 170.788,59.156 170.788,57.998 171.486,57.299 178.448,57.299 U1.8@179.606,58.46
  other v1: 140.387,99.1
D11/MOSI: P1.4 U5.15 | length 30.3
  Top Layer w0.145: P1.4@145.699,65.092 144.392,66.4 142.787,66.4 142.088,67.101 142.088,68.099 142.688,68.701 143.688,68.701 152.388,77.401 159.987,77.401 160.788,78.201 161.387,78.201 161.892,77.693 U5.15@161.892,77.081
D12/MISO: P1.1 U5.16 | length 21.8
  Top Layer w0.145: P1.1@143.159,67.632 152.608,77.082 U5.16@161.093,77.082
D13/SCK: LED.1 P1.3 U5.17 | length 34.5
  Top Layer w0.145: LED.1@138.43,67.443 140.809,67.442 P1.3@143.159,65.092 ; P1.3@143.159,65.092 144.252,64 146.188,64 146.688,64.5 146.688,65.6 145.888,66.4 145.288,66.4 144.488,67.2 144.488,68.201 145.187,68.899 146.287,68.899 146.688,69.301 146.688,70.101 152.987,76.4 159.286,76.4 159.518,76.169 U5.17@159.518,75.491
DIR485: R5.1 R93.1 U1.14 U6.15 U8.2 U8.3 | length 65.8
  Top Layer w0.145: U6.15@130.815,90.925 131.412,90.925 131.437,90.9 v1(132.187,90.9) ; v1(138.187,91.6) 139.187,92.6 139.187,98.8 140.087,99.699 141.489,99.699 144.585,96.6 145.786,96.6 146.452,97.266 U8.2@146.452,97.68 ; U8.2@146.452,97.68 U8.3@147.722,97.68 147.722,95.365 R5.1@147.787,95.3 R93.1@147.787,93.8 ; R93.1@147.887,93.75 R93.1@147.787,93.8 ; 150.296,93.8 R93.1@147.787,93.8 ; 150.296,93.8 153.41,90.678 154.41,90.678 156.587,88.5 165.087,88.5 165.587,88 165.587,83 v1(166.887,81.7)
  Bottom Layer w0.145: v1(132.187,90.9) 137.487,90.9 v1(138.187,91.6) ; v1(166.887,81.7) 172.367,81.7 U1.14@174.527,83.86
DN1: CN8.6 TO_PC.A7 TO_PC.B7 | length 29.1
  Top Layer w0.145: CN8.6@196.317,114.94 197.287,115.91 197.287,140.935 ; TO_PC.A7@197.337,140.985 197.287,140.935 ; 198.337,140.985 198.287,141.035 198.287,141.7 198.087,141.9 197.587,141.9 197.287,141.6 197.287,140.935
DN2: CN9.6 CN10.6 DC/AUX.A7 DC/AUX.B7 | length 36.6
  Top Layer w0.145: 196.838,60.916 196.838,60.151 197.087,59.9 197.587,59.9 197.836,60.149 197.836,60.916 197.687,63.6 197.686,68.191 CN10.6@198.857,69.36
  Bottom Layer w0.145: CN9.6@198.857,93.36 197.787,92.29 197.787,70.43 CN10.6@198.857,69.36
DP1: CN8.5 TO_PC.A6 TO_PC.B6 | length 30.2
  Top Layer w0.145: v1(196.687,139.9) 196.837,140.05 TO_PC.B6@196.837,140.985 ; CN8.5@198.857,114.94 197.587,116.21 197.587,139.6 v1(197.887,139.9) ; v1(197.887,139.9) 197.887,140.935 TO_PC.A6@197.837,140.985 197.837,139.95 v1(197.887,139.9)
  Bottom Layer w0.145: v1(196.687,139.9) v1(197.887,139.9)
DP2: CN9.5 CN10.5 DC/AUX.A6 DC/AUX.B6 | length 36.1
  Top Layer w0.145: CN10.5@196.317,69.36 197.338,68.34 197.338,60.916 ; 198.337,60.915 198.387,60.965 v1(198.387,62)
  Bottom Layer w0.145: CN9.5@196.317,93.36 197.487,92.19 197.487,70.53 CN10.5@196.317,69.36 ; v1(197.187,62) v1(198.387,62)
F3_1: F3.1 FCAN1.1 J3.1 | length 26.5
  Top Layer w0.3: J3.1@154.516,103.631 155.786,104.901 157.788,104.901 159.586,103.1 162.088,103.1 165.088,106.1 168.637,106.1 ; 168.408,106.1 168.837,106.1 169.937,105 169.937,103.55 171.285,102.201 FCAN1.1@174.138,102.201 ; F3.1@174.187,100.5 FCAN1.1@174.187,102.152
FCAN_1: F2.1 FCAN.1 J2.1 | length 21.2
  Top Layer w0.145: F2.1@172.787,116.9 173.587,116.9 174.438,116.049 FCAN.1@174.438,114.901
  Top Layer w0.5: J2.1@156.757,121.73 162.057,121.73 164.987,118.8 170.987,118.8 172.787,117 F2.1@172.787,116.9
FCAN_2: FCAN.2 R71.1 | length 1.7
  Top Layer w0.145: R71.1@171.087,114.9 FCAN.2@172.737,114.9
FGNSS_2: FGNSS.2 R64.1 | length 1.8
  Top Layer w0.145: FGNSS.2@67.137,63 67.137,61.45 R64.1@67.287,61.3
FINP_2: FINP.2 R73.1 | length 2
  Top Layer w0.145: FINP.2@67.637,102.5 R73.1@69.687,102.5
FROT_2: FROT.2 R75.1 | length 1.6
  Top Layer w0.145: FROT.2@186.637,83.5 186.787,83.65 R75.1@186.787,85
FSER_2: FSER.2 R76.2 | length 1.6
  Top Layer w0.145: FSER.2@175.837,124 R76.2@177.487,124
FWAS_2: FWAS.2 R74.1 | length 1.6
  Top Layer w0.145: R74.1@67.387,120 67.537,119.85 FWAS.2@67.537,118.5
